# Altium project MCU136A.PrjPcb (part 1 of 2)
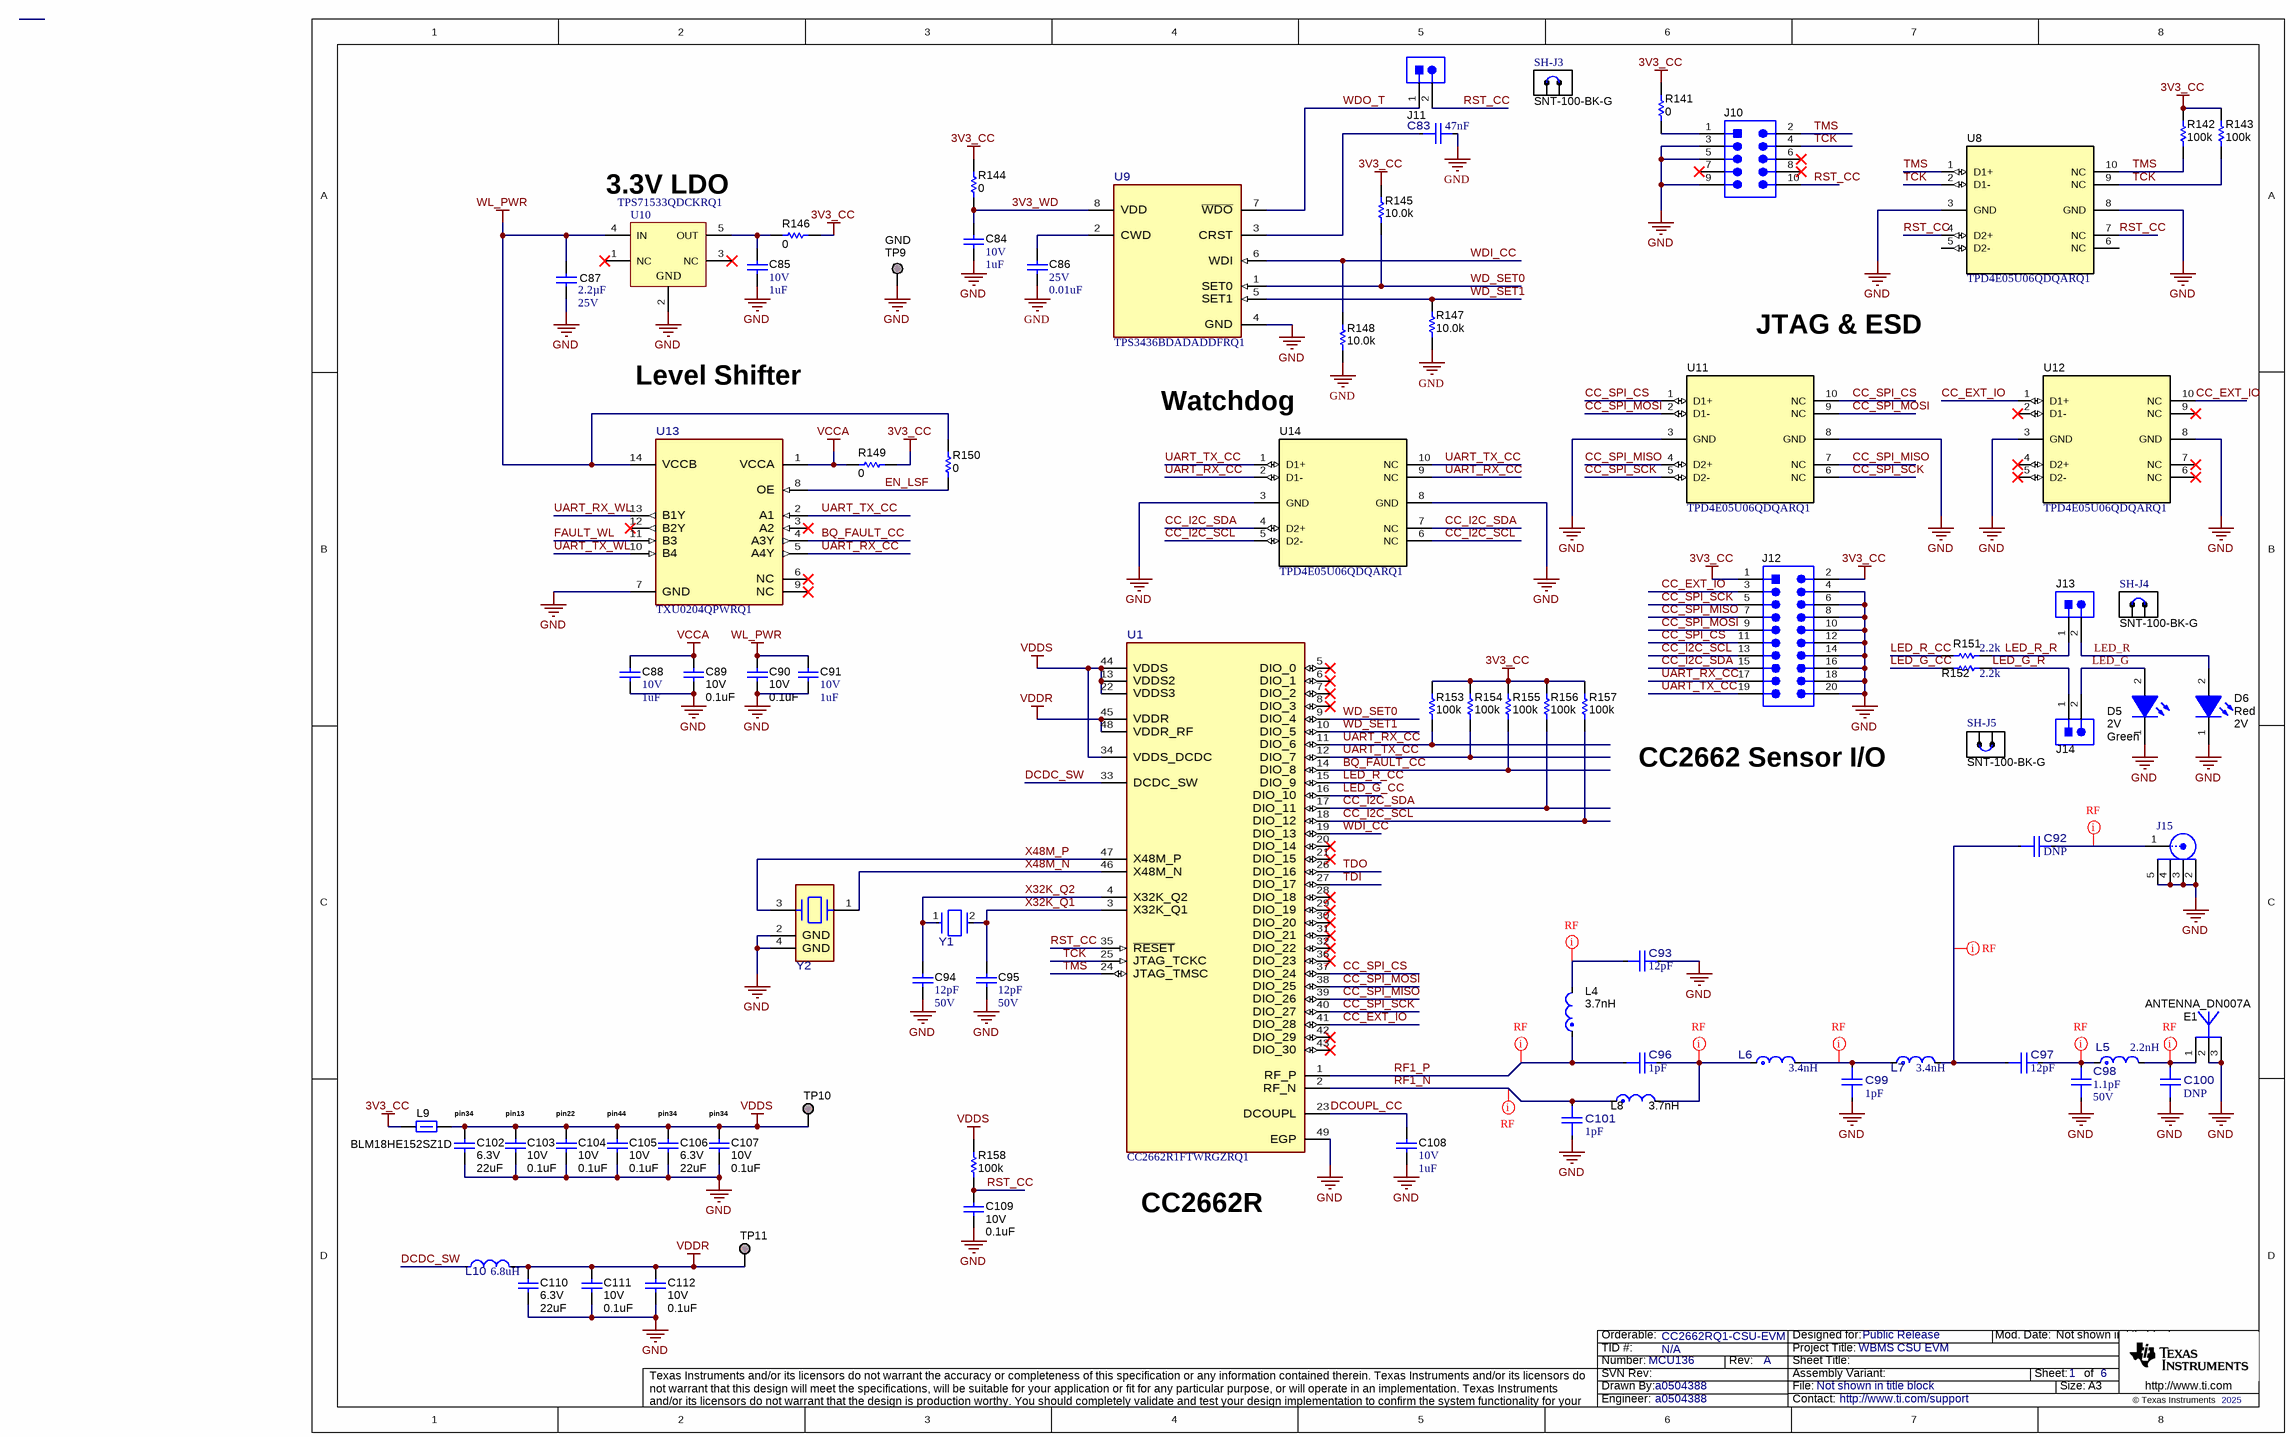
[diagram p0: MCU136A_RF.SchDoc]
CopyrightYear: 2025; DrawnBy: a0504388; EVM_orderable: CC2662RQ1-CSU-EVM; PCB_Layout: a0504388; PCB_Rev: A; PRJ_Customer: Public Release; PRJ_Engineer: a0504388; PRJ_Number: MCU136; PRJ_Title: WBMS CSU EVM; SCH_Rev: A; TechSupport: http://www.ti.com/support; TID: N/A
6 sheets, 391 parts. Net scope: global (net labels, ports and power ports of the same name join across sheets).
Board file: MCU136A.PcbDoc
Sheets:
  MCU136A_RF.SchDoc
  MCU136A_BQ7971x.SchDoc
  MCU136A_Connector.SchDoc
  MCU136A_Resistive_Ladder.SchDoc
  MCU136A_Communication.SchDoc
  MCU136A_Hardware.SchDoc

## Sheet MCU136A_RF.SchDoc
size A3; Date: Not shown in title block; ApprovedBy: Not shown in title block; CheckedBy: Not shown in title block; Author: Not shown in title block; CompanyName: Not shown in title block; Engineer: Not shown in title block; Organization: Not shown in title block; Address1: Not shown in title block; Address2: Not shown in title block; Address3: Not shown in title block; Address4: Not shown in title block; DocumentNumber: 5; Revision: Use project parameter SCH_Rev; SheetNumber: 1; SheetTotal: 6; PageSetup: Record=PageOptions¦CenterHorizontal=True¦CenterVertical=True¦PrintScale=1.00¦XCorrection=1.00¦YCorrection=1.00¦PrintKind=0¦BorderSize=5000000¦LeftOffset=0¦BottomOffset=0¦Orientation=2¦PaperLength=1000¦PaperWidth=1000¦Scale=100¦PaperSource=15¦PrintQuality=600¦MediaType=1¦DitherType=10¦PaperKind=Letter¦PrintScaleMode=1

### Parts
C83  ValueDisplayed: 47nF  [FP-GCM155R71E473KA55D_0402-MFG]  (hidden comment: GCM155R71E473KA55D)
C84  VDC_V: 10V  ValueDisplayed: 1uF  [0402_070]  (hidden comment: GCM155C71A105KE38D)
C85  VDC_V: 10V  ValueDisplayed: 1uF  [0402_070]  (hidden comment: GCM155C71A105KE38D)
C86  VDC_V: 25V  ValueDisplayed: 0.01uF  [0402]  (hidden comment: GCM155R71E103KA37D)
C87  Cap_F: 2.2µF  VDC_V: 25V  [0805_HV]  (hidden comment: GCM21BR71E225KA73L)
C88  VDC_V: 10V  ValueDisplayed: 1uF  [0402_070]  (hidden comment: GCM155C71A105KE38D)
C89  VDC_V: 10V  ValueDisplayed: 0.1uF  [0402]  (hidden comment: GCM155R71A104KA55D)
C90  VDC_V: 10V  ValueDisplayed: 0.1uF  [0402]  (hidden comment: GCM155R71A104KA55D)
C91  VDC_V: 10V  ValueDisplayed: 1uF  [0402_070]  (hidden comment: GCM155C71A105KE38D)
C92  ValueDisplayed: DNP  [FP-GCQ0335C1H120GB01D_0201-MFG]  (hidden comment: GCQ0335C1H120GB01D)
C93  ValueDisplayed: 12pF  [FP-GCQ0335C1H120GB01D_0201-MFG]  (hidden comment: GCQ0335C1H120GB01D)
C94  ValueDisplayed: 12pF  VDC_V: 50V  [0402]  (hidden comment: GCM1555C1H120JA16J)
C95  ValueDisplayed: 12pF  VDC_V: 50V  [0402]  (hidden comment: GCM1555C1H120JA16J)
C96  ValueDisplayed: 1pF  [FP-GCQ0335C1H1R0WB01D_0201-MFG]  (hidden comment: GCQ0335C1H1R0WB01D)
C97  ValueDisplayed: 12pF  [FP-GCQ0335C1H120GB01D_0201-MFG]  (hidden comment: GCQ0335C1H120GB01D)
C98  ValueDisplayed: 1.1pF  VDC_V: 50V  [FP-GCQ0335C1H1R1BB01D_0201-MFG]  (hidden comment: GCQ0335C1H1R1BB01D)
C99  ValueDisplayed: 1pF  [FP-GCQ0335C1H1R0WB01D_0201-MFG]  (hidden comment: GCQ0335C1H1R0WB01D)
C100  ValueDisplayed: DNP  [FP-GCQ0335C1H1R0WB01D_0201-MFG]  (hidden comment: GCQ0335C1H1R0WB01D)
C101  ValueDisplayed: 1pF  [FP-GCQ0335C1H1R0WB01D_0201-MFG]  (hidden comment: GCQ0335C1H1R0WB01D)
C102  VDC_V: 6.3V  ValueDisplayed: 22uF  [0805_HV]  (hidden comment: GCM21BD70J226ME36L)
C103  VDC_V: 10V  ValueDisplayed: 0.1uF  [0402]  (hidden comment: GCM155R71A104KA55D)
C104  VDC_V: 10V  ValueDisplayed: 0.1uF  [0402]  (hidden comment: GCM155R71A104KA55D)
C105  VDC_V: 10V  ValueDisplayed: 0.1uF  [0402]  (hidden comment: GCM155R71A104KA55D)
C106  VDC_V: 6.3V  ValueDisplayed: 22uF  [0805_HV]  (hidden comment: GCM21BD70J226ME36L)
C107  VDC_V: 10V  ValueDisplayed: 0.1uF  [0402]  (hidden comment: GCM155R71A104KA55D)
C108  VDC_V: 10V  ValueDisplayed: 1uF  [0402_070]  (hidden comment: GCM155C71A105KE38D)
C109  VDC_V: 10V  ValueDisplayed: 0.1uF  [0402]  (hidden comment: GCM155R71A104KA55D)
C110  VDC_V: 6.3V  ValueDisplayed: 22uF  [0805_HV]  (hidden comment: GCM21BD70J226ME36L)
C111  VDC_V: 10V  ValueDisplayed: 0.1uF  [0402]  (hidden comment: GCM155R71A104KA55D)
C112  VDC_V: 10V  ValueDisplayed: 0.1uF  [0402]  (hidden comment: GCM155R71A104KA55D)
D5  value Green  Value2: 2V  [WL-SMCW_GREEN]  (hidden comment: 150060VS75000)
D6  value Red  Vf_V: 2V  [WL-SMCW_RED]  (hidden comment: 150060RS75000)
E1  ANTENNA_DN007A  [ANTENNA_DN007A]  (net tie)
J10  FTSH-105-01-F-DV-K  [Samtec_FTSH-105-01-x-DV-K]  (value not drawn)
J11  PEC02SAAN  [CONN_PEC02SAAN]  (value not drawn)
J12  TSW-110-07-G-D  [TSW-110-07-G-D]  (value not drawn)
J13  PEC02SAAN  [CONN_PEC02SAAN]  (value not drawn)
J14  PEC02SAAN  [CONN_PEC02SAAN]  (value not drawn)
J15  SMA-J-P-H-ST-MT1  [Samtec_SMA-J-P-H-ST-MT1]  (value not drawn)
L4  value 3.7nH  [FP-LQP03TN3N7BZ2J_0603-MFG]  (hidden comment: LQP03TN3N7BZ2J)
L5  value 2.2nH  [FP-LQP03TN2N2BZ2B_0201 (0603)-MFG]  (hidden comment: LQP03TN2N2BZ2B)
L6  value 3.4nH  [FP-LQP03TN3N4BZ2B_0201 (0603)-MFG]  (hidden comment: LQP03TN3N4BZ2B)
L7  value 3.4nH  [FP-LQP03TN3N4BZ2B_0201 (0603)-MFG]  (hidden comment: LQP03TN3N4BZ2B)
L8  value 3.7nH  [FP-LQP03TN3N7BZ2J_0603-MFG]  (hidden comment: LQP03TN3N7BZ2J)
L9  BLM18HE152SZ1D  [0603]
L10  value 6.8uH  [FP-MLZ2012N6R8LTD25_0805-MFG]  (hidden comment: MLZ2012N6R8LTD25)
R141  ValueDisplayed: 0  [0402]  (hidden comment: CRCW04020000Z0ED)
R142  ValueDisplayed: 100k  [0402]  (hidden comment: CRCW0402100KFKED)
R143  ValueDisplayed: 100k  [0402]  (hidden comment: CRCW0402100KFKED)
R144  ValueDisplayed: 0  [0402]  (hidden comment: CRCW04020000Z0ED)
R145  ValueDisplayed: 10.0k  [0402]  (hidden comment: CRCW040210K0FKED)
R146  ValueDisplayed: 0  [0402]  (hidden comment: CRCW04020000Z0ED)
R147  ValueDisplayed: 10.0k  [0402]  (hidden comment: CRCW040210K0FKED)
R148  ValueDisplayed: 10.0k  [0402]  (hidden comment: CRCW040210K0FKED)
R149  ValueDisplayed: 0  [0402]  (hidden comment: CRCW04020000Z0ED)
R150  ValueDisplayed: 0  [0402]  (hidden comment: CRCW04020000Z0ED)
R151  ValueDisplayed: 2.2k  [0402]  (hidden comment: CRCW04022K20JNED)
R152  ValueDisplayed: 2.2k  [0402]  (hidden comment: CRCW04022K20JNED)
R153  ValueDisplayed: 100k  [0402]  (hidden comment: CRCW0402100KFKED)
R154  ValueDisplayed: 100k  [0402]  (hidden comment: CRCW0402100KJNED)
R155  ValueDisplayed: 100k  [0402]  (hidden comment: CRCW0402100KFKED)
R156  ValueDisplayed: 100k  [0402]  (hidden comment: CRCW0402100KFKED)
R157  ValueDisplayed: 100k  [0402]  (hidden comment: CRCW0402100KFKED)
R158  ValueDisplayed: 100k  [0402]  (hidden comment: CRCW0402100KJNED)
SH-J3  SNT-100-BK-G  [SNT-100-BK-G]
SH-J4  SNT-100-BK-G  [SNT-100-BK-G]
SH-J5  SNT-100-BK-G  [SNT-100-BK-G]
TP9  GND  [Keystone1598-2]
TP10  TP_SM_1MM  [TP_SM_1MM]  (value not drawn)  (no BOM)
TP11  TP_SM_1MM  [TP_SM_1MM]  (value not drawn)  (no BOM)
U1  CC2662R1FTWRGZRQ1  [RGZ0048R-MFG]
U8  TPD4E05U06QDQARQ1  [DQA0010A]
U9  TPS3436BDADADDFRQ1  [DDF0008A-MFG]
U10  TPS71533QDCKRQ1  [DCK0005A_N]
U11  TPD4E05U06QDQARQ1  [DQA0010A]
U12  TPD4E05U06QDQARQ1  [DQA0010A]
U13  TXU0204QPWRQ1  [PW0014A-MFG]
U14  TPD4E05U06QDQARQ1  [DQA0010A]
Y1  DST1610A 7BG03276AAC  [FP-DST1610A 7BG03276AAC_SMD2-MFG]  (value not drawn)
Y2  CX2016DB48000C0FRLC1  [FP-CX2016DB48000C0FRLC1_SMT4_2MM05_1MM65-MFG]  (value not drawn)

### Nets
3V3_CC: J12.1 J12.2 L9.1 R141.1 R142.2 R143.2 R144.1 R145.2 R146.2 R149.2 R153.2 R154.2 R155.2 R156.2 R157.2
GND: C83.2 C84.2 C85.2 C86.2 C87.1 C88.2 C89.2 C90.2 C91.2 C93.1 C94.2 C95.2 C98.1 C99.1 C100.1 C101.1 C102.2 C103.2 C104.2 C105.2 C106.2 C107.2 C108.2 C109.2 C110.2 C111.2 C112.2 D5.1(K) D6.1(K) E1.2 E1.3 J10.3 J10.5 J10.9 J12.4 J12.6 J12.8 J12.10 J12.12 J12.14 J12.16 J12.18 J12.20 J15.2 J15.3 J15.4 J15.5 R147.1 R148.1 TP9.1 U1.49(EGP) U8.3(GND) U8.8(GND) U9.4(GND) U10.2(GND) U11.3(GND) U11.8(GND) U12.3(GND) U12.8(GND) U13.7(GND) U14.3(GND) U14.8(GND) Y2.2(GND) Y2.4(GND)
VCCA: C88.1 C89.1 R149.1 U13.1(VCCA)
VDDR: C110.1 C111.1 C112.1 L10.2 TP11.1 U1.45(VDDR) U1.48(VDDR_RF)
VDDS: C102.1 C103.1 C104.1 C105.1 C106.1 C107.1 L9.2 R158.2 TP10.1 U1.13(VDDS2) U1.22(VDDS3) U1.34(VDDS_DCDC) U1.44(VDDS)
WL_PWR: C87.2 C90.1 C91.1 R150.1 U10.4(IN) U13.14(VCCB)
3V3_WD: C84.1 R144.2 U9.8(VDD)
BQ_FAULT_CC: R155.1 U1.14(DIO_8) U13.4(A3Y)
CC_EXT_IO: J12.3 U1.41(DIO_28) U12.1(D1+) U12.10(NC)
CC_I2C_SCL: J12.13 R157.1 U1.18(DIO_12) U14.5(D2-) U14.6(NC)
CC_I2C_SDA: J12.15 R156.1 U1.17(DIO_11) U14.4(D2+) U14.7(NC)
CC_SPI_CS: J12.11 U1.37(DIO_24) U11.1(D1+) U11.10(NC)
CC_SPI_MISO: J12.7 U1.39(DIO_26) U11.4(D2+) U11.7(NC)
CC_SPI_MOSI: J12.9 U1.38(DIO_25) U11.2(D1-) U11.9(NC)
CC_SPI_SCK: J12.5 U1.40(DIO_27) U11.5(D2-) U11.6(NC)
DCDC_SW: L10.1 U1.33(DCDC_SW)
DCOUPL_CC: C108.1 U1.23(DCOUPL)
EN_LSF: R150.2 U13.8(OE)
FAULT_WL: U13.11(B3)
LED_G: D5.2(A) J14.2
LED_G_CC: R152.2 U1.16(DIO_10)
LED_G_R: J14.1 R152.1
LED_R: D6.2(A) J13.2
LED_R_CC: R151.2 U1.15(DIO_9)
LED_R_R: J13.1 R151.1
RF1_N: C101.2 L8.1 U1.2(RF_N)
RF1_P: C96.1 L4.1 U1.1(RF_P)
RST_CC: C109.1 J10.10 J11.2 R158.1 U1.35(~{RESET}) U8.4(D2+) U8.7(NC)
TCK: J10.4 R143.1 U1.25(JTAG_TCKC) U8.2(D1-) U8.9(NC)
TDI: U1.27(DIO_17)
TDO: U1.26(DIO_16)
TMS: J10.2 R142.1 U1.24(JTAG_TMSC) U8.1(D1+) U8.10(NC)
UART_RX_CC: J12.17 R153.1 U1.11(DIO_6) U13.5(A4Y) U14.2(D1-) U14.9(NC)
UART_RX_WL: U13.13(B1Y)
UART_TX_CC: J12.19 R154.1 U1.12(DIO_7) U13.2(A1) U14.1(D1+) U14.10(NC)
UART_TX_WL: U13.10(B4)
WD_SET0: R145.1 U1.9(DIO_4) U9.1(SET0)
WD_SET1: R147.2 U1.10(DIO_5) U9.5(SET1)
WDI_CC: R148.2 U1.19(DIO_13) U9.6(WDI)
WDO_T: J11.1 U9.7(~{WDO})
X32K_Q1: C95.1 U1.3(X32K_Q1) Y1.2
X32K_Q2: C94.1 U1.4(X32K_Q2) Y1.1
X48M_N: U1.46(X48M_N) Y2.1
X48M_P: U1.47(X48M_P) Y2.3
NetC83_1: C83.1 U9.3(CRST)
NetC85_1: C85.1 R146.1 U10.5(OUT)
NetC86_1: C86.1 U9.2(CWD)
NetC92_1: C92.1 C97.1 L7.2
NetC92_2: C92.2 J15.1
NetC93_2: C93.2 L4.2
NetC96_2: C96.2 L6.1 L8.2
NetC97_2: C97.2 C98.2 L5.1
NetC99_2: C99.2 L6.2 L7.1
NetC100_2: C100.2 E1.1 L5.2
NetJ10_1: J10.1 R141.2

Not connected (* = marked no-connect by the designer): J10 6* 7* 8*; U1 5(DIO_0)* 6(DIO_1)* 7(DIO_2)* 8(DIO_3)* 20(DIO_14)* 21(DIO_15)* 28(DIO_18)* 29(DIO_19)* 30(DIO_20)* 31(DIO_21)* 32(DIO_22)* 36(DIO_23)* 42(DIO_29)* 43(DIO_30)*; U8 5(D2-) 6(NC); U10 1(NC)* 3(NC)*; U12 2(D1-)* 4(D2+)* 5(D2-)* 6(NC)* 7(NC)* 9(NC)*; U13 3(A2)* 6(NC)* 9(NC)* 12(B2Y)*

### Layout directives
net class RF: NetC92_1, NetC92_2, NetC93_2, NetC96_2, NetC97_2, NetC99_2, NetC100_2, RF1_N, RF1_P

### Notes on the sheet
- (near U10) 3.3V LDO
- Level Shifter
- JTAG & ESD
- Watchdog
- CC2662 Sensor I/O
- pin34
- (near C103) pin13
- (near C104) pin22
- (near C105) pin44
- (near C106) pin34
- (near C107) pin34
- (near U1) CC2662R

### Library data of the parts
C83 = CMP-0120705-1: Ceramic Capacitor for Automotive 47nF ±10% 25VDC X7R 0402 Paper T/R; Manufacturer: Murata; AEC Grade: Grade 1; AEC Qualified: Yes; SizeZ_mm: 0.55mm; TempCo: 15%; Tolerance_%: 0.1%; VDC_V: 25V
C84 C85 C88 C91 C108 = CMP-0006349-2: CAP, CERM, 1 uF, 10 V, +/- 10%, X7S, AEC-Q200 Grade 1, 0402; Manufacturer: MuRata; TaMin_C: -55°C; Polarized: N; SizeAreaWB_mm2: 3; Value1: Unknown; U/M: EA; Value: 1uF; TaMax_C: 125°C; SizeZ_mm: 0.7; SizeX_mm: 1; SizeY_mm: 0.5; Cap_Case: 0402; AEC Qualified: Y; Cap_F: 1µF; AEC Category: Q200
C86 = CMP-0006352-2: CAP, CERM, 0.01 uF, 25 V, +/- 10%, X7R, 0402; Manufacturer: MuRata; TaMin_C: -55°C; Polarized: N; SizeAreaWB_mm2: 3; Value1: Unknown; U/M: EA; Value: 0.01uF; TaMax_C: 125°C; SizeZ_mm: 0.6; SizeX_mm: 1; SizeY_mm: 0.5; Cap_F: 10nF; AEC Category: Q200
C87 = CMP-0083622-1: CAP, CERM, 2.2 µF, 25 V,+/- 10%, X7R, AEC-Q200 Grade 1, 0805; Manufacturer: MuRata; TaMin_C: -55°C; Polarized: N; SizeAreaWB_mm2: 6.75; U/M: EA; Value: 2.2uF; TaMax_C: 125°C; SizeZ_mm: 1.45; SizeX_mm: 2; SizeY_mm: 1.25; Cap_Case: 0805; SizeArea_mm2: 2.5; AEC Qualified: Y; AEC Grade: 1; AEC Category: Q200
C89 C90 C103-C105 C107 C109 C111 C112 = CMP-0006350-2: CAP, CERM, 0.1 uF, 10 V, +/- 10%, X7R, AEC-Q200 Grade 1, 0402; Manufacturer: MuRata; TaMin_C: -55°C; Polarized: N; SizeAreaWB_mm2: 3; Value1: Unknown; U/M: EA; Value: 0.1uF; TaMax_C: 125°C; SizeZ_mm: 0.6; SizeX_mm: 1; SizeY_mm: 0.5; AEC Qualified: Y; Cap_F: 100nF; AEC Category: Q200
C92 C93 C97 = CMP-0120430-1: High Q Chip Multilayer Ceramic Capacitors for Automotive 12pF ±2% 50Vdc 0201; Manufacturer: Murata; AEC Grade: Grade 1; AEC Qualified: Yes; SizeZ_mm: 0.33mm; TempCo: 30ppm/°C; VDC_V: 50V; Temperature Characteristic: C0G
C94 C95 = CMP-0085816-1: CAP, CERM, 12 pF, 50 V,+/- 5%, C0G/NP0, AEC-Q200 Grade 1, 0402; Manufacturer: MuRata; AEC Category: Q200; SizeX_mm: 1; TaMin_C: -55°C; SizeAreaWB_mm2: 3; SizeArea_mm2: 0.5; SizeZ_mm: 0.6; Polarized: N; U/M: EA; Value: 12pF; TaMax_C: 125°C; AEC Qualified: Y
C96 C99-C101 = CMP-0120431-1: 1pF ±0.05pF 50V Ceramic Capacitor C0G 0201 (0603 Metric); Manufacturer: Murata; AEC Grade: Grade 1; AEC Qualified: Yes; SizeZ_mm: 0.33mm; TempCo: 30ppm/°C
C98 = CMP-0124483-1: Cap Ceramic 1.1pF ±0.1pF 50V C0G 0201 AECQ200; Manufacturer: Murata; AEC Grade: Grade 1; AEC Qualified: Yes; SizeZ_mm: 0.33mm; TempCo: 30ppm/°C
C102 C106 C110 = CMP-0008015-1: CAP, CERM, 22 uF, 6.3 V, +/- 20%, X7T, AEC-Q200 Grade 1, 0805; Manufacturer: MuRata; TaMin_C: -55°C; Polarized: N; SizeAreaWB_mm2: 6.75; Value1: Unknown; U/M: EA; Value: 22uF; TaMax_C: 125°C; SizeZ_mm: 1.45; SizeX_mm: 2; SizeY_mm: 1.25; Cap_Case: 0805; SizeArea_mm2: 2.5; AEC Qualified: Y; Cap_F: 22µF; AEC Grade: 1; AEC Category: Q200
D5 = CMP-0002894-2: LED, Green, SMD; Manufacturer: Wurth Elektronik; Type: AlInGaP; Io_A: 20mA; Value1: W
D6 = CMP-0002947-3: LED, Red, SMD; Manufacturer: Wurth Elektronik; Value1: 0.072W; Angle: 140; Tjmax_C: 85°C; Type: AlInGaP; Vr_V: 5V; Io_A: 30mA; Power_TotalModule: 72mW
E1 = CMP-0001734-1: 2.4GHz PCB Antenna.  There is nothing to buy or mount.
J10 = CMP-0075670-2: Header (Shrouded), 1.27mm, 5x2, Gold, SMT; Manufacturer: Samtec; Pitch_mm: 1.27; Gender: Male; Cert_CSA: Y; Current_A: 3.3A; Row_Count: 2
J11 J13 J14 = CMP-0002337-1: Header, 100mil, 2x1, Tin, TH; Manufacturer: Sullins Connector Solutions; CNHeader: TRUE; Current_A: 3A; Green_Lifecycle: Not Set; Shrouded: N; Gender: Male; Green_REACh: Incomplete; Voltage_V: 1.8kV; Row_Count: 1; Pitch_mm: 2.54; CT: FALSE; Cert_UL: Y
J12 = CMP-0075421-2: Header, 100mil, 10x2, Gold, TH; Manufacturer: Samtec; Pitch_mm: 2.54; Cert_VDE: N; Gender: Male; Cert_CSA: Y; Voltage_V: 550V; Green_REACh: Passed; Current_A: 6.3A; Green_Lifecycle: Active; Row_Count: 2
J15 = CMP-0080462-1: JACK, SMA, 50 Ohm, Gold, TH; Manufacturer: Samtec; Gender: Female; Voltage_V: 335V
L4 L8 = CMP-0090225-1: Inductor 3.7nH, Size Code 0603 (0201), High Q, Wide Variation. AEC-Q200; Manufacturer: Murata; DCR_ohm: 0.3; AEC Qualified: Yes; TaMax_C: +125°C; Q Factor: 14; Tolerance_%: 0.1nH; Self Resonant Frequency: 6GHz; AEC Grade: Grade 1; TaMin_C: -55°C; Test Frequency: 500MHz; Irms: 400mA; SizeZ_mm: 0.33mm
L5 = CMP-0124485-1: Film type RF Inductor for Automotive 2.2nH ±0.1nH 600mA 0.15Ω 0201 (0603); Manufacturer: Murata; AEC Grade: Grade 1; AEC Qualified: Yes; DCR_ohm: 0.15; SizeZ_mm: 0.33mm; Q Factor: 14; Self Resonant Frequency: 11GHz; Test Frequency: 500MHz
L6 L7 = CMP-0037178-1: Film type RF Inductor for Automotive 3.4nH ±0.1nH 450mA 0.25Ω 0201 (0603); Manufacturer: Murata; AEC Grade: Grade 1; AEC Qualified: Yes; DCR_ohm: 0.25; SizeZ_mm: 0.33mm; Q Factor: 14; Self Resonant Frequency: 7GHz; Test Frequency: 500MHz
L9 = CMP-0080768-1: Ferrite Bead, 1500 ohm @ 100 MHz, 0.5 A, 0603; Manufacturer: MuRata; SizeAreaWB_mm2: 4.68; SizeArea_mm2: 1.28; SizeZ_mm: 1; Imax_A: 5dA; ZTyp@100MHz_Ohm: 1.5k; SizeY_mm: 0.8; Value2: 0.5A; Value1: 0.5 ohm; DCR_ohm: 5d; SizeX_mm: 1.6
L10 = CMP-0121210-1: Shielded Multilayer Inductor 6.8uH ±20% 550mA 325mΩ AEC-Q200 SMD 0805; Manufacturer: TDK; AEC Grade: Grade 1; AEC Qualified: Yes; DCR_ohm: 0.325; Ind_H: 6.8µH; Isat: 110mA; Material: Ferrite; SizeZ_mm: 1.05mm; Shrouded: true; Test Frequency: 2MHz
R141 R144 R146 R149 R150 = CMP-0026822-3: RES, 0, 5%, 0.063 W, AEC-Q200 Grade 0, 0402; Manufacturer: Vishay-Dale; Power_W: 63mW; TempCo: 200 ppm/C; Value_Code: 0000; Value: 0; EIA_Code: E24; SizeX_mm: 1; SizeY_mm: 0.5; SizeZ_mm: 0.6; Value2: 0.063W; AEC Qualified: Y; VDC_V: 50V; AEC Category: Q200
R142 R143 R153 R155-R157 = CMP-0025950-3: RES, 100 k, 1%, 0.063 W, AEC-Q200 Grade 0, 0402; Manufacturer: Vishay-Dale; Power_W: 63mW; TempCo: 100 ppm/C; Value: 100k; EIA_Code: E96; SizeX_mm: 1; SizeY_mm: 0.5; SizeZ_mm: 0.6; Value2: 0.063W; AEC Qualified: Y; VDC_V: 50V; AEC Category: Q200; AEC Grade: 0
R145 R147 R148 = CMP-0025958-3: RES, 10.0 k, 1%, 0.063 W, AEC-Q200 Grade 0, 0402; Manufacturer: Vishay-Dale; Power_W: 63mW; TempCo: 100 ppm/C; Value_Code: 10k0; Value: 10.0k; EIA_Code: E96; Res_ohm: 10k; SizeX_mm: 1; SizeY_mm: 0.5; SizeZ_mm: 0.6; Value2: 0.063W; AEC Qualified: Y; VDC_V: 50V; AEC Category: Q200; AEC Grade: 0
R151 R152 = CMP-0026890-5: RES, 2.2 k, 5%, 0.063 W, AEC-Q200 Grade 0, 0402; Manufacturer: Vishay-Dale; Power_W: 63mW; TempCo: 200 ppm/C; Value_Code: 2k20; Value: 2.2k; EIA_Code: E24; SizeX_mm: 1; SizeY_mm: 0.5; SizeZ_mm: 0.6; Value2: 0.063W; AEC Qualified: Y; VDC_V: 50V; AEC Category: Q200; AEC Grade: 0
R154 R158 = CMP-0026823-3: RES, 100 k, 5%, 0.063 W, AEC-Q200 Grade 0, 0402; Manufacturer: Vishay-Dale; Power_W: 63mW; TempCo: 200 ppm/C; Value: 100k; EIA_Code: E24; SizeX_mm: 1; SizeY_mm: 0.5; SizeZ_mm: 0.6; Value2: 0.063W; AEC Qualified: Y; VDC_V: 50V; AEC Category: Q200; AEC Grade: 0
SH-J3-SH-J5 = CMP-0003623-3: Shunt, 100mil, Gold plated, Black; Alternate PartNumber: 969102-0000-DA; Manufacturer: Samtec; Alternate Manufacturer: 3M; Value: 1x2; Note: You can "mate" this to a header by matching the designator.  i.e. use SH-J3 for header J3
TP9 = CMP-0055121-1: Terminal, Turret, TH, Triple; Manufacturer: Keystone; PartNumber: 1598-2; CT: FALSE; Green_REACh: Passed; CompType: Turret Terminal; Green_Lifecycle: Active
TP10 TP11 = CMP-0003825-1: 1mm Test Point, SMT; Manufacturer: Any
U1 = CMP-0121950-1: Automotive qualified SimpleLink wireless MCU for use in wireless battery management systems; Manufacturer: Texas Instruments; SizeZ_mm: 1mm; AEC Qualified: Yes; AEC Grade: Grade 2; Core Architecture: ARM Cortex-M4F; Data Bus Width: 32bits; Frequency_Fixed: 48MHz; Interface: I2C,SPI,UART,I2S; Max Supply Voltage: 3.63V; Memory Size: 352KBytes; Memory Type: FLASH; Min Supply Voltage: 1.8V; Number Of A/D Converters: 1; Number Of Adc Channels: 8; Number Of I/Os: 31; Number Of Pwm Channels: 9; Number Of Spi Channels: 2; Number Of Timers/Counters: 11; Ram Size: 80KBytes; Standoff Height: 0mm; TaMax_C: +105°C; TaMin_C: -40°C
U8 U11 U12 U14 = CMP-0073599-3: Automotive 4-Channel ESD Protection Solution for SuperSpeed (up to 5 Gbps) Interface, DQA0010A (USON-10); Manufacturer: Texas Instruments; SizeZ_mm: 0.55; SizeX_mm: 1.0; SizeY_mm: 2.5; CompType: IC; SizeAreaWB_mm2: 7.0; AEC Category: Q200; AEC Qualified: Y
U9 = CMP-0120735-1: Automotive Nano IQ Precision Window Watchdog Timer; Manufacturer: Texas Instruments; SizeZ_mm: 1.1mm; AEC Qualified: Yes; AEC Grade: Grade 1; Max Supply Voltage: 6V; Min Supply Voltage: 900mV; Nominal Supply Current: 0.25uA; Number Of Outputs: 1; Output Voltage: 0-6V; Reset Type: Active Low; Standoff Height: 0mm; TaMax_C: +125°C; TaMin_C: -40°C; Watchdog Timer: true
U10 = CMP-0035727-2: Single Output Automotive LDO, 50 mA, Fixed 3.3 V Output, 3 to 24 V Input, 5-pin SC70 (DCK), -40 to 125 degC, Green (RoHS & no Sb/Br); Manufacturer: Texas Instruments; Vdo(Typ)(mV): 415; Vout Adj(Min)(V): 3.3; Vin(Max)(V): 24; Iq(Typ)(mA): 0.003; SubFamily: Single Channel LDO; Accuracy(%): 4; Vin(Min)(V): 3; Iout(Max)(A): 0.05; AEC Category: Q200; AEC Qualified: Y; CompType: IC; SizeAreaWB_mm2: 9.3; SizeArea_mm2: 4.2; SizeX_mm: 2.1; SizeY_mm: 2.0; SizeZ_mm: 1.1
U13 = CMP-0120806-1: Automotive 4-Bit Fixed Direction Voltage-Level Translator with SchmittTrigger Inputs and 3-State Outputs; Manufacturer: Texas Instruments; SizeZ_mm: 1.2mm; AEC Qualified: Yes; AEC Grade: Grade 1; Data Rate: 200Mbits/s; Nominal Supply Current: 2.5uA; Number Of Inputs: 4; PositionCount: 1; Propagation Delay: 8ns; Standoff Height: 0.05mm; TaMax_C: +125°C; TaMin_C: -40°C; TJmax_C: +150°C; V A Max: 5.5V; V A Min: 1.08V
Y1 = CMP-0121920-1: SMD Tuning Fork Crystal Resonators / kHz Band Crystal Resonators 32.768KHZ 7PF ±20PPM; Manufacturer: DAISHINKU; SizeZ_mm: 0.5mm; AEC Qualified: Yes; AEC Grade: Grade 1; Esr: 70k; TJmax_C: +125°C
Y2 = CMP-0121714-1: Quartz Crystal 48 MHz 7pF 10ppm; Manufacturer: KYOCERA AVX; Frequency Stability: 20ppm; Frequency_Fixed: 48MHz; SizeZ_mm: 0.5mm; AEC Qualified: Yes; AEC Grade: Grade 2; Esr: 30

## Sheet MCU136A_BQ7971x.SchDoc
size A3; Date: Not shown in title block; ApprovedBy: Not shown in title block; CheckedBy: Not shown in title block; Author: Not shown in title block; CompanyName: Not shown in title block; Engineer: Not shown in title block; Organization: Not shown in title block; Address1: Not shown in title block; Address2: Not shown in title block; Address3: Not shown in title block; Address4: Not shown in title block; DocumentNumber: 2; Revision: Use project parameter SCH_Rev; SheetNumber: 2; SheetTotal: 6; PageSetup: Record=PageOptions¦CenterHorizontal=True¦CenterVertical=True¦PrintScale=1.00¦XCorrection=1.00¦YCorrection=1.00¦PrintKind=0¦BorderSize=5000000¦LeftOffset=0¦BottomOffset=0¦Orientation=2¦PaperLength=1000¦PaperWidth=1000¦Scale=100¦PaperSource=15¦PrintQuality=600¦MediaType=1¦DitherType=10¦PaperKind=Letter¦PrintScaleMode=1
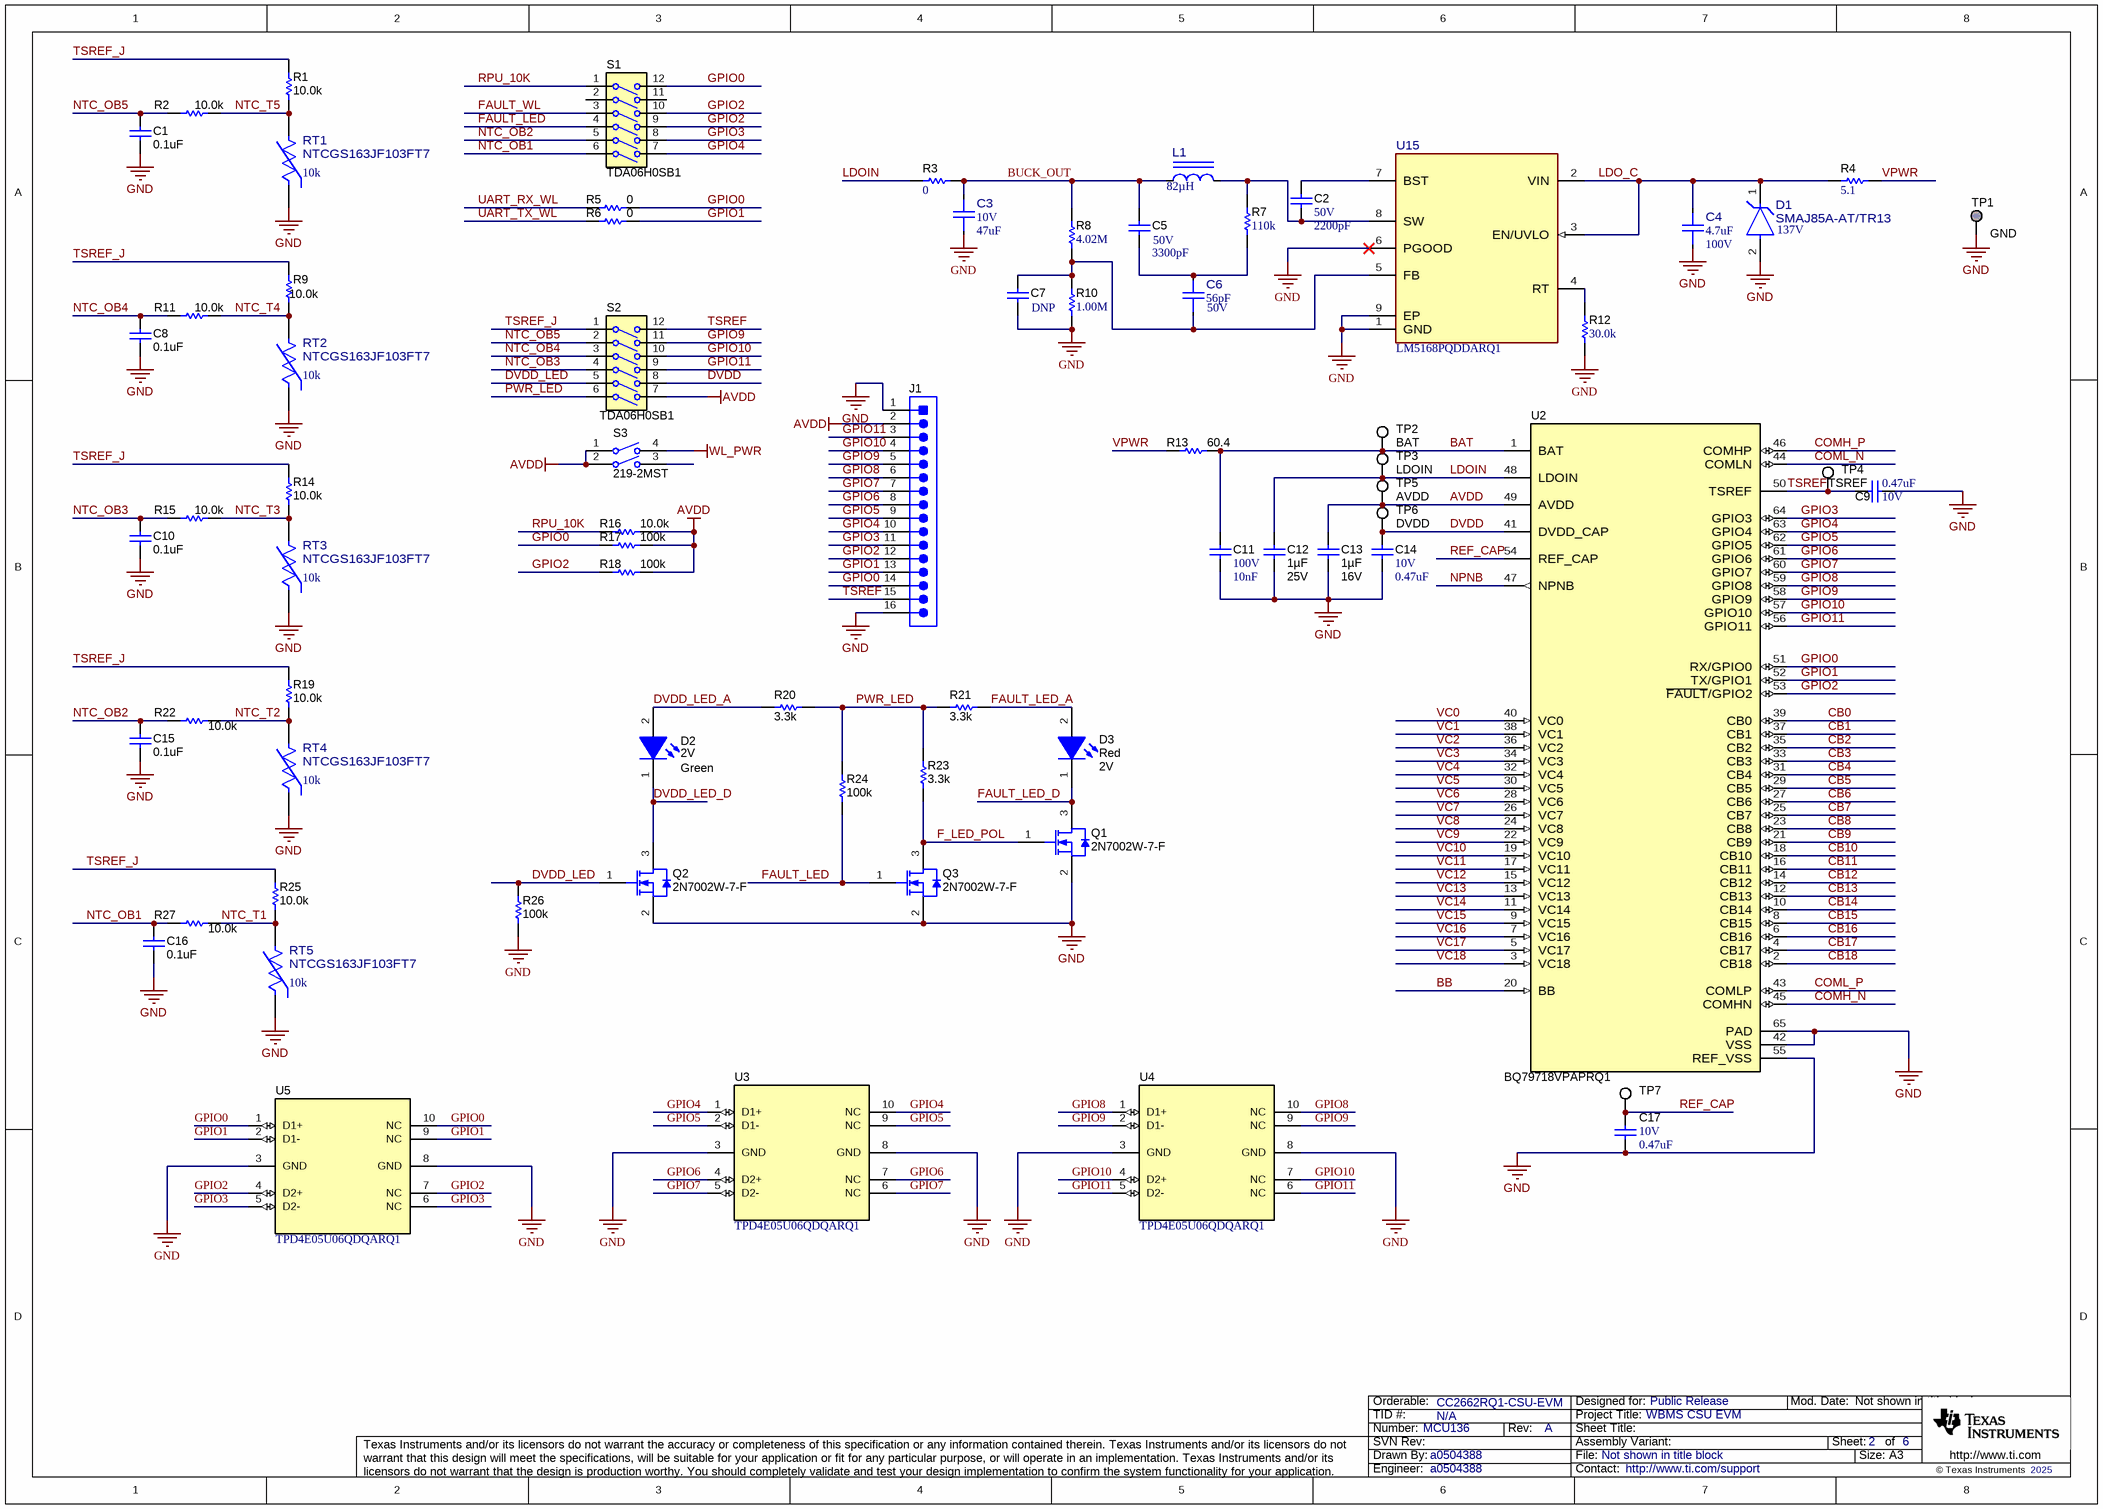
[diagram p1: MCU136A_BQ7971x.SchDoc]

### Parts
C1  ValueDisplayed: 0.1uF  [0402]  (hidden comment: GCM155R71H104KE02D)
C2  VDC_V: 50V  ValueDisplayed: 2200pF  [0402]  (hidden comment: GCM155R71H222KA37D)
C3  VDC_V: 10V  ValueDisplayed: 47uF  [FP-GCM32EC71A476KE02K_1210-MFG]  (hidden comment: GCM32EC71A476KE02K)
C4  ValueDisplayed: 4.7uF  VDC_V: 100V  [FP-GCJ32DC72A475KE01L_1210-MFG]  (hidden comment: GCJ32DC72A475KE01L)
C5  VDC_V: 50V  ValueDisplayed: 3300pF  [0402]  (hidden comment: GCM155R71H332KA37D)
C6  ValueDisplayed: 56pF  VDC_V: 50V  [FP-GCM1555C1H560FA16D_0402-MFG]  (hidden comment: GCM1555C1H560FA16D)
C7  Cap_F: DNP  [0603]  (hidden comment: GCM188R72A103KA37J)
C8  ValueDisplayed: 0.1uF  [0402]  (hidden comment: GCM155R71H104KE02D)
C9  VDC_V: 10V  ValueDisplayed: 0.47uF  [0402]  (hidden comment: GCM155C71A474KE36D)
C10  ValueDisplayed: 0.1uF  [0402]  (hidden comment: GCM155R71H104KE02D)
C11  VDC_V: 100V  Cap_F: 10nF  [0603]  (hidden comment: GCM188R72A103KA37J)
C12  ValueDisplayed: 1µF  VDC_V: 25V  [0805_HV]  (hidden comment: GCJ21BL81E105KA01L)
C13  Cap_F: 1µF  VDC_V: 16V  [0603]  (hidden comment: GCM188R71C105KA64D)
C14  VDC_V: 10V  ValueDisplayed: 0.47uF  [0402]  (hidden comment: GCM155C71A474KE36D)
C15  ValueDisplayed: 0.1uF  [0402]  (hidden comment: GCM155R71H104KE02D)
C16  ValueDisplayed: 0.1uF  [0402]  (hidden comment: GCM155R71H104KE02D)
C17  VDC_V: 10V  ValueDisplayed: 0.47uF  [0402]  (hidden comment: GCM155C71A474KE36D)
D1  SMAJ85A-AT/TR13  Clamping Voltage: 137V  [FP-SMAJ85A-AT/TR13_SMA-MFG]
D2  value Green  Value2: 2V  [WL-SMCW_GREEN]  (hidden comment: 150060VS75000)
D3  value Red  Vf_V: 2V  [WL-SMCW_RED]  (hidden comment: 150060RS75000)
J1  TSW-116-07-G-S  [TSW-116-07-G-S]  (value not drawn)
L1  Ind_H: 82µH  [FP-SRR0735HA-820M-NO_KEEPOUTS-MFG]  (hidden comment: SRR0735HA-820M)
Q1  2N7002W-7-F  [SOT-323]
Q2  2N7002W-7-F  [SOT-323]
Q3  2N7002W-7-F  [SOT-323]
R1  ValueDisplayed: 10.0k  [0402]  (hidden comment: CRCW040210K0FKED)
R2  ValueDisplayed: 10.0k  [0402]  (hidden comment: CRCW040210K0FKED)
R3  ValueDisplayed: 0  [0603]  (hidden comment: CRCW06030000Z0EA)
R4  ValueDisplayed: 5.1  [2010]  (hidden comment: CRCW20105R10JNEF)
R5  ValueDisplayed: 0  [0402]  (hidden comment: CRCW04020000Z0ED)
R6  ValueDisplayed: 0  [0402]  (hidden comment: CRCW04020000Z0ED)
R7  ValueDisplayed: 110k  [0402]  (hidden comment: CRCW0402110KFKED)
R8  ValueDisplayed: 4.02M  [0402]  (hidden comment: CRCW04024M02FKED)
R9  ValueDisplayed: 10.0k  [0402]  (hidden comment: CRCW040210K0FKED)
R10  ValueDisplayed: 1.00M  [0402]  (hidden comment: CRCW04021M00FKED)
R11  ValueDisplayed: 10.0k  [0402]  (hidden comment: CRCW040210K0FKED)
R12  ValueDisplayed: 30.0k  [0402]  (hidden comment: CRCW040230K0FKED)
R13  ValueDisplayed: 60.4  [0603]  (hidden comment: CRCW060360R4FKEA)
R14  ValueDisplayed: 10.0k  [0402]  (hidden comment: CRCW040210K0FKED)
R15  ValueDisplayed: 10.0k  [0402]  (hidden comment: CRCW040210K0FKED)
R16  ValueDisplayed: 10.0k  [0402]  (hidden comment: CRCW040210K0FKED)
R17  ValueDisplayed: 100k  [0402]  (hidden comment: CRCW0402100KFKED)
R18  ValueDisplayed: 100k  [0402]  (hidden comment: CRCW0402100KFKED)
R19  ValueDisplayed: 10.0k  [0402]  (hidden comment: CRCW040210K0FKED)
R20  ValueDisplayed: 3.3k  [0402]  (hidden comment: CRCW04023K30JNED)
R21  ValueDisplayed: 3.3k  [0402]  (hidden comment: CRCW04023K30JNED)
R22  ValueDisplayed: 10.0k  [0402]  (hidden comment: CRCW040210K0FKED)
R23  ValueDisplayed: 3.3k  [0402]  (hidden comment: CRCW04023K30JNED)
R24  ValueDisplayed: 100k  [0402]  (hidden comment: CRCW0402100KFKED)
R25  ValueDisplayed: 10.0k  [0402]  (hidden comment: CRCW040210K0FKED)
R26  ValueDisplayed: 100k  [0402]  (hidden comment: CRCW0402100KFKED)
R27  ValueDisplayed: 10.0k  [0402]  (hidden comment: CRCW040210K0FKED)
RT1  NTCGS163JF103FT7  value 10k  [FP-NTCGS163JF103FT7_0603-MFG]
RT2  NTCGS163JF103FT7  value 10k  [FP-NTCGS163JF103FT7_0603-MFG]
RT3  NTCGS163JF103FT7  value 10k  [FP-NTCGS163JF103FT7_0603-MFG]
RT4  NTCGS163JF103FT7  value 10k  [FP-NTCGS163JF103FT7_0603-MFG]
RT5  NTCGS163JF103FT7  value 10k  [FP-NTCGS163JF103FT7_0603-MFG]
S1  TDA06H0SB1  [SW_TDA06H0SB1]
S2  TDA06H0SB1  [SW_TDA06H0SB1]
S3  219-2MST  [SW_219-2MST]
TP1  GND  [Keystone1598-2]
TP2  BAT  [Keystone5012]
TP3  LDOIN  [Keystone5012]
TP4  TSREF  [Keystone5012]
TP5  AVDD  [Keystone5012]
TP6  DVDD  [Keystone5012]
TP7  REF_CAP  [Keystone5012]  (value not drawn)
U2  BQ79718VPAPRQ1  [PAP0064F-MFG]
U3  TPD4E05U06QDQARQ1  [DQA0010A]
U4  TPD4E05U06QDQARQ1  [DQA0010A]
U5  TPD4E05U06QDQARQ1  [DQA0010A]
U15  LM5168PQDDARQ1  [DDA0008E-MFG]

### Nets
AVDD: C13.1 J1.2 R16.1 R17.2 R18.2 S2.7(6A) S3.1 S3.2 TP5.1 U2.49(AVDD)
GND: C1.2 C3.1 C4.1 C7.2 C8.2 C9.2 C10.2 C11.2 C12.2 C13.2 C14.2 C15.2 C16.2 C17.2 D1.2(ANODE) J1.1 J1.16 Q1.2(S) Q2.2(S) Q3.2(S) R10.1 R12.1 R26.1 RT1.1 RT2.1 RT3.1 RT4.1 RT5.1 TP1.1 U2.42(VSS) U2.55(REF_VSS) U2.65(PAD) U3.3(GND) U3.8(GND) U4.3(GND) U4.8(GND) U5.3(GND) U5.8(GND) U15.1(GND) U15.6(PGOOD) U15.9(EP)
WL_PWR: S3.4
BAT: C11.1 R13.2 TP2.1 U2.1(BAT)
BB: U2.20(BB)
BUCK_OUT: C3.2 C5.1 L1.1 R3.2 R8.2
CB0: U2.39(CB0)
CB1: U2.37(CB1)
CB2: U2.35(CB2)
CB3: U2.33(CB3)
CB4: U2.31(CB4)
CB5: U2.29(CB5)
CB6: U2.27(CB6)
CB7: U2.25(CB7)
CB8: U2.23(CB8)
CB9: U2.21(CB9)
CB10: U2.18(CB10)
CB11: U2.16(CB11)
CB12: U2.14(CB12)
CB13: U2.12(CB13)
CB14: U2.10(CB14)
CB15: U2.8(CB15)
CB16: U2.6(CB16)
CB17: U2.4(CB17)
CB18: U2.2(CB18)
COMH_N: U2.45(COMHN)
COMH_P: U2.46(COMHP)
COML_N: U2.44(COMLN)
COML_P: U2.43(COMLP)
DVDD: C14.1 S2.8(5A) TP6.1 U2.41(DVDD_CAP)
DVDD_LED: Q2.1(G) R26.2 S2.5
DVDD_LED_A: D2.2(A) R20.2
DVDD_LED_D: D2.1(K) Q2.3(D)
F_LED_POL: Q1.1(G) Q3.3(D) R23.1
FAULT_LED: Q3.1(G) R24.1 S1.4
FAULT_LED_A: D3.2(A) R21.1
FAULT_LED_D: D3.1(K) Q1.3(D)
FAULT_WL: S1.3
GPIO0: J1.14 R5.2 R17.1 S1.12(1A) U2.51(RX/GPIO0) U5.1(D1+) U5.10(NC)
GPIO1: J1.13 R6.2 U2.52(TX/GPIO1) U5.2(D1-) U5.9(NC)
GPIO2: J1.12 R18.1 S1.9(4A) S1.10(3A) U2.53(~{FAULT}/GPIO2) U5.4(D2+) U5.7(NC)
GPIO3: J1.11 S1.8(5A) U2.64(GPIO3) U5.5(D2-) U5.6(NC)
GPIO4: J1.10 S1.7(6A) U2.63(GPIO4) U3.1(D1+) U3.10(NC)
GPIO5: J1.9 U2.62(GPIO5) U3.2(D1-) U3.9(NC)
GPIO6: J1.8 U2.61(GPIO6) U3.4(D2+) U3.7(NC)
GPIO7: J1.7 U2.60(GPIO7) U3.5(D2-) U3.6(NC)
GPIO8: J1.6 U2.59(GPIO8) U4.1(D1+) U4.10(NC)
GPIO9: J1.5 S2.11(2A) U2.58(GPIO9) U4.2(D1-) U4.9(NC)
GPIO10: J1.4 S2.10(3A) U2.57(GPIO10) U4.4(D2+) U4.7(NC)
GPIO11: J1.3 S2.9(4A) U2.56(GPIO11) U4.5(D2-) U4.6(NC)
LDO_C: C4.2 D1.1(CATHODE) R4.1 U15.2(VIN) U15.3(EN/UVLO)
LDOIN: C12.1 R3.1 TP3.1 U2.48(LDOIN)
NPNB: U2.47(NPNB)
NTC_OB1: C16.1 R27.1 S1.6
NTC_OB2: C15.1 R22.1 S1.5
NTC_OB3: C10.1 R15.1 S2.4
NTC_OB4: C8.1 R11.1 S2.3
NTC_OB5: C1.1 R2.1 S2.2
NTC_T1: R25.1 R27.2 RT5.2
NTC_T2: R19.1 R22.2 RT4.2
NTC_T3: R14.1 R15.2 RT3.2
NTC_T4: R9.1 R11.2 RT2.2
NTC_T5: R1.1 R2.2 RT1.2
PWR_LED: R20.1 R21.2 R23.2 R24.2 S2.6
REF_CAP: C17.1 TP7.1 U2.54(REF_CAP)
RPU_10K: R16.2 S1.1
TSREF: C9.1 J1.15 S2.12(1A) TP4.1 U2.50(TSREF)
TSREF_J: R1.2 R9.2 R14.2 R19.2 R25.2 S2.1
UART_RX_WL: R5.1
UART_TX_WL: R6.1
VC0: U2.40(VC0)
VC1: U2.38(VC1)
VC2: U2.36(VC2)
VC3: U2.34(VC3)
VC4: U2.32(VC4)
VC5: U2.30(VC5)
VC6: U2.28(VC6)
VC7: U2.26(VC7)
VC8: U2.24(VC8)
VC9: U2.22(VC9)
VC10: U2.19(VC10)
VC11: U2.17(VC11)
VC12: U2.15(VC12)
VC13: U2.13(VC13)
VC14: U2.11(VC14)
VC15: U2.9(VC15)
VC16: U2.7(VC16)
VC17: U2.5(VC17)
VC18: U2.3(VC18)
VPWR: R4.2 R13.1
NetC2_1: C2.1 U15.7(BST)
NetC2_2: C2.2 L1.2 R7.2 U15.8(SW)
NetC5_2: C5.2 C6.2 R7.1
NetC6_1: C6.1 C7.1 R8.1 R10.2 U15.5(FB)
NetR12_2: R12.2 U15.4(RT)

Not connected (* = marked no-connect by the designer): S1 2 11(2A); S3 3

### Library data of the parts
C1 C8 C10 C15 C16 = CMP-0006356-2: CAP, CERM, 0.1 uF, 50 V, +/- 10%, X7R, AEC-Q200 Grade 1, 0402; Manufacturer: MuRata; TaMin_C: -55°C; Polarized: N; SizeAreaWB_mm2: 3; Value1: Unknown; U/M: EA; Value: 0.1uF; TaMax_C: 125°C; SizeZ_mm: 0.6; SizeX_mm: 1; SizeY_mm: 0.5; Value2: 50V; AEC Qualified: Y; Cap_F: 100nF; AEC Category: Q200
C2 = CMP-0006357-2: CAP, CERM, 2200 pF, 50 V, +/- 10%, X7R, AEC-Q200 Grade 1, 0402; Manufacturer: MuRata; TaMin_C: -55°C; Polarized: N; SizeAreaWB_mm2: 3; Value1: Unknown; U/M: EA; Value: 2200pF; TaMax_C: 125°C; SizeZ_mm: 0.6; SizeX_mm: 1; SizeY_mm: 0.5; AEC Qualified: Y; Cap_F: 2.2nF; AEC Category: Q200
C3 = CMP-0096011-1: Ceramic Capacitor for Automotive 47uF ±10% 10VDC X7S 1210 Embossed T/R; Manufacturer: Murata; SizeZ_mm: 2.7mm; Value: 47µF; TempCo: 22%; AEC Qualified: Yes; AEC Grade: Grade 1
C4 = CMP-0093675-1: 4.7uF ±10% 100V Ceramic Capacitor X7S 1210 (3225 Metric); Manufacturer: Murata; Value: 4.7µF; AEC Qualified: Yes; TempCo: 22%; SizeZ_mm: 2.3mm; AEC Grade: Grade 1
C5 = CMP-0006359-2: CAP, CERM, 3300 pF, 50 V, +/- 10%, X7R, AEC-Q200 Grade 1, 0402; Manufacturer: MuRata; TaMin_C: -55°C; Polarized: N; SizeAreaWB_mm2: 3; Value1: Unknown; U/M: EA; Value: 3300pF; TaMax_C: 125°C; SizeZ_mm: 0.6; SizeX_mm: 1; SizeY_mm: 0.5; AEC Qualified: Y; Cap_F: 3.3nF; AEC Category: Q200
C6 = CMP-0121510-1: Ceramic Capacitor for Automotive 56pF ±1% 50VDC C0G 0402 Paper T/R; Manufacturer: Murata; AEC Grade: Grade 1; AEC Qualified: Yes; SizeZ_mm: 0.55mm; TempCo: 30ppm/°C; Tolerance_%: 0.01%
C7 = CMP-0084773-1: CAP, CERM, 0.01 µF, 100 V,+/- 10%, X7R, AEC-Q200 Grade 1, 0603; Manufacturer: MuRata; AEC Qualified: Y; SizeX_mm: 1.6; TaMin_C: -55°C; SizeArea_mm2: 1.28; AEC Category: Q200; ValueDisplayed: 0.01µF; Value2: 100V; SizeZ_mm: 1; Value: 0.01uF; Polarized: N; SizeAreaWB_mm2: 4.68; TaMax_C: 125°C; SizeY_mm: 0.8; U/M: EA
C9 C14 C17 = CMP-0064967-2: CAP, CERM, 0.47 uF, 10 V,+/- 10%, X7S, 0402; Manufacturer: MuRata; TaMin_C: -55°C; Polarized: N; SizeAreaWB_mm2: 3; Value1: Unknown; U/M: EA; Value: 0.47uF; TaMax_C: 125°C; SizeZ_mm: 0.6; SizeX_mm: 1; SizeY_mm: 0.5; Cap_F: 470nF; AEC Category: Q200
C11 = CMP-0084773-1: CAP, CERM, 0.01 µF, 100 V,+/- 10%, X7R, AEC-Q200 Grade 1, 0603; Manufacturer: MuRata; AEC Qualified: Y; SizeX_mm: 1.6; TaMin_C: -55°C; SizeArea_mm2: 1.28; AEC Category: Q200; ValueDisplayed: 0.01µF; SizeZ_mm: 1; Value: 0.01uF; Polarized: N; SizeAreaWB_mm2: 4.68; TaMax_C: 125°C; SizeY_mm: 0.8; U/M: EA
C12 = CMP-0860704-1: CAP, CERM, 1 µF, 25 V,+/- 10%, X8L, AEC-Q200 Grade 0, 0805; Manufacturer: MuRata; AEC Qualified: Y; SizeY_mm: 1.25; TaMax_C: 150°C; U/M: EA; SizeX_mm: 2; AEC Category: Q200; AEC Grade: 0; Polarized: N; SizeZ_mm: 1.45; Cap_Case: 0805; TaMin_C: -55°C; SizeAreaWB_mm2: 6.75; SizeArea_mm2: 2.5; Value: 1uF
C13 = CMP-0007136-5: CAP, CERM, 1 uF, 16 V, +/- 10%, X7R, AEC-Q200 Grade 1, 0603; Manufacturer: MuRata; TaMin_C: -55°C; Polarized: N; SizeAreaWB_mm2: 4.68; Value1: Unknown; U/M: EA; Value: 1uF; TaMax_C: 125°C; SizeZ_mm: 1; SizeX_mm: 1.6; SizeY_mm: 0.8; SizeArea_mm2: 1.28; AEC Qualified: Y; AEC Category: Q200
D1 = CMP-0121790-1: 137V Clamp 2.9A Ipp Tvs Diode Surface Mount DO-214AC (SMA); Manufacturer: YAGEO; AEC Qualified: Yes; SizeZ_mm: 2.5mm; VRWM: 85V; Ppk: 400W; AEC Grade: Grade 0; Breakdown Voltage: 94.4V; Direction: Unidirectional; Number Of Channels: 1; TJmax_C: +150°C
D2 = CMP-0002894-2: as D5 on sheet MCU136A_RF
D3 = CMP-0002947-3: as D6 on sheet MCU136A_RF
J1 = CMP-0075430-1: Header, 100mil, 16x1, Gold, TH; Manufacturer: Samtec; Pitch_mm: 2.54; Cert_VDE: N; Gender: Male; Cert_CSA: Y; Current_A: 6.3A; Voltage_V: 550V; CT: False; Row_Count: 1; CNHeader: True
L1 = CMP-0125208-2: 82 µH Shielded Drum Core, Wirewound Inductor 630 mA 480mOhm Max Nonstandard; Manufacturer: Bourns; Alternate PartNumber: SRR0735A-820M; AEC Grade: Grade 0; AEC Qualified: Yes; DCR_ohm: 0.48; Irms: 0.63A; Isat: 0.65A; Material: Ferrite; SizeZ_mm: 3.7mm; Value: 82uH; Shrouded: true; Test Frequency: 1kHz; Tolerance_%: 20%
Q1-Q3 = CMP-0000776-1: MOSFET, N-CH, 60 V, 0.115 A, SOT-323; Alternate Manufacturer: None; Manufacturer: Diodes Inc.; SizeZ_mm: 1.1; ChType: N; Value1: 7; VdsMax_V: 60V; SizeX_mm: 2.2; Vgs_V: 20V; Value: 60V; Rdson45_ohm: 7.5; SizeArea_mm2: 4.84; AEC Category: Q101; IdsMax_A: 1.15dA; SizeAreaWB_mm2: 10.24; U/M: EA
R1 R2 R9 R11 R14-R16 R19 R22 R25 R27 = CMP-0025958-3: as R145 on sheet MCU136A_RF
R3 = CMP-0025697-4: RES, 0, 5%, 0.1 W, AEC-Q200 Grade 0, 0603; Manufacturer: Vishay-Dale; Power_W: 100mW; TempCo: 200 ppm/C; Value_Code: 0000; Value: 0; EIA_Code: E24; SizeX_mm: 1.6; SizeY_mm: 0.8; SizeZ_mm: 1; Value2: 0.1W; SizeArea_mm2: 1.28; AEC Qualified: Y; VDC_V: 75V; AEC Category: Q200
R4 = CMP-0016161-3: RES, 5.1, 5%, 0.75 W, AEC-Q200 Grade 0, 2010; Manufacturer: Vishay-Dale; Power_W: 750mW; TempCo: 200 ppm/C; Value_Code: 5R10; Value: 5.1; EIA_Code: E24; SizeX_mm: 5; SizeY_mm: 2.5; SizeZ_mm: 1.66; Value2: 0.75W; SizeArea_mm2: 12.5; AEC Qualified: Y; VDC_V: 400V; AEC Grade: 0; AEC Category: Q200
R5 R6 = CMP-0026822-3: as R141 on sheet MCU136A_RF
R7 = CMP-0025967-3: RES, 110 k, 1%, 0.063 W, AEC-Q200 Grade 0, 0402; Manufacturer: Vishay-Dale; Power_W: 63mW; TempCo: 100 ppm/C; Value: 110k; EIA_Code: E96; SizeY_mm: 0.5; SizeZ_mm: 0.6; Value2: 0.063W; AEC Qualified: Y; VDC_V: 50V; AEC Category: Q200; SizeX_mm: 1; AEC Grade: 0
R8 = CMP-0026415-2: RES, 4.02 M, 1%, 0.063 W, AEC-Q200 Grade 0, 0402; Manufacturer: Vishay-Dale; Power_W: 63mW; TempCo: 100 ppm/C; Value_Code: 4M02; Value: 4.02Meg; EIA_Code: E96; SizeX_mm: 1; SizeY_mm: 0.5; SizeZ_mm: 0.6; Value2: 0.063W; AEC Qualified: Y; VDC_V: 50V; AEC Category: Q200; AEC Grade: 0
R10 = CMP-0026100-2: RES, 1.00 M, 1%, 0.063 W, AEC-Q200 Grade 0, 0402; Manufacturer: Vishay-Dale; Power_W: 63mW; TempCo: 100 ppm/C; Value_Code: 1M00; Value: 1.00Meg; EIA_Code: E96; Res_ohm: 1M; SizeX_mm: 1; SizeY_mm: 0.5; SizeZ_mm: 0.6; Value2: 0.063W; AEC Qualified: Y; VDC_V: 50V; AEC Category: Q200; AEC Grade: 0
R12 = CMP-0078244-2: RES, 30.0 k, 1%, 0.063 W, AEC-Q200 Grade 0, 0402; Manufacturer: Vishay-Dale; Power_W: 63mW; Green_Lifecycle: Active; TempCo: 100 ppm/C; Value_Code: 30k0; Green_REACh: Passed; Value: 30.0k; Res_ohm: 30k; SizeX_mm: 1; SizeY_mm: 0.5; SizeZ_mm: 0.6; Value2: 0.063W; AEC Qualified: Y; VDC_V: 50V; AEC Grade: 0; AEC Category: Q200
R13 = CMP-0022533-4: RES, 60.4, 1%, 0.1 W, AEC-Q200 Grade 0, 0603; Manufacturer: Vishay-Dale; Power_W: 100mW; TempCo: 100 ppm/C; Value_Code: 60R4; Value: 60.4; EIA_Code: E96; SizeX_mm: 1.6; SizeY_mm: 0.8; SizeZ_mm: 1; Value2: 0.1W; SizeArea_mm2: 1.28; CompType: Resistor; AEC Qualified: Y; VDC_V: 75V; AEC Category: Q200; AEC Grade: 0
R17 R18 R24 R26 = CMP-0025950-3: as R142 on sheet MCU136A_RF
R20 R21 R23 = CMP-0026918-5: RES, 3.3 k, 5%, 0.063 W, AEC-Q200 Grade 0, 0402; Manufacturer: Vishay-Dale; Power_W: 63mW; TempCo: 200 ppm/C; Value_Code: 3k30; Value: 3.3k; EIA_Code: E24; SizeX_mm: 1; SizeY_mm: 0.5; SizeZ_mm: 0.6; Value2: 0.063W; AEC Qualified: Y; VDC_V: 50V; AEC Category: Q200; AEC Grade: 0
RT1-RT5 = CMP-0124490-2: NTC Thermistor 10k 0603 (1608 Metric); Manufacturer: TDK; Power_W: 100mW; SizeZ_mm: 0.9mm; Tolerance_%: 1%; AEC Grade: Grade 1; AEC Qualified: Yes; B 25 100: 3453K; B 25 50: 3380K; B 25 75: 3422K; B 25 85: 3435K; Max Current: 0.31mA; Res_ohm: 10kΩ; VDC_V: 5V
S1 S2 = CMP-0002278-1: DIP Switch, SPST, 6Pos, Slide, SMT; Manufacturer: C&K Components; CurrentRating_mA: 25A; PositionCount: 6; VDC_V: 24V; SwitchFunction: Off-On
S3 = CMP-0002290-1: Switch, SPST, Slide, Off-On, 2 Pos, 0.1A, 20V, SMD; Manufacturer: CTS Electrocomponents; CurrentRating_mA: 100A; PositionCount: 2; SizeX_mm: 9.91; SizeY_mm: 6.55; SizeZ_mm: 4.23; SizeArea_mm2: 64.9105; SizeAreaWB_mm2: 101.8305
TP1 = CMP-0055121-1: as TP9 on sheet MCU136A_RF
TP2-TP7 = CMP-0055149-1: Test Point, Multipurpose, White, TH; PartNumber: 5012; Manufacturer: Keystone; ContactFinish: Silver; CNHeader: FALSE; Green_Lifecycle: Active; Green_REACh: Passed; CT: TRUE
U2 = CMP-0091255-1: BQ79718-Q1; Manufacturer: Texas Instruments; SizeZ_mm: 1.2mm; Standoff Height: 0.05mm
U3-U5 = CMP-0073599-3: as U8 on sheet MCU136A_RF
U15 = CMP-0092718-1: 0.3-A,120-V, Step-Down Converter with Fly-buck Capability; Manufacturer: Texas Instruments; Max Supply Voltage: 115V; SizeZ_mm: 1.7mm; Switching Frequency: 1MHz; Max Duty Cycle: 100%; Number Of Outputs: 1; Nominal Supply Current: 10-420uA; Min Supply Voltage: 6V; Standoff Height: 0mm; AEC Qualified: Yes; Output Type: AdjustableProgrammable; Switching Topology: Buck; TJmax_C: +150°C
